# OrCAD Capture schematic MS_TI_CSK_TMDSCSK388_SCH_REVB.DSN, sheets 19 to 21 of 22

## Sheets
19 19.ETHERNET,HDMI & USB: size C; title: ETHERNET,HDMI & USB
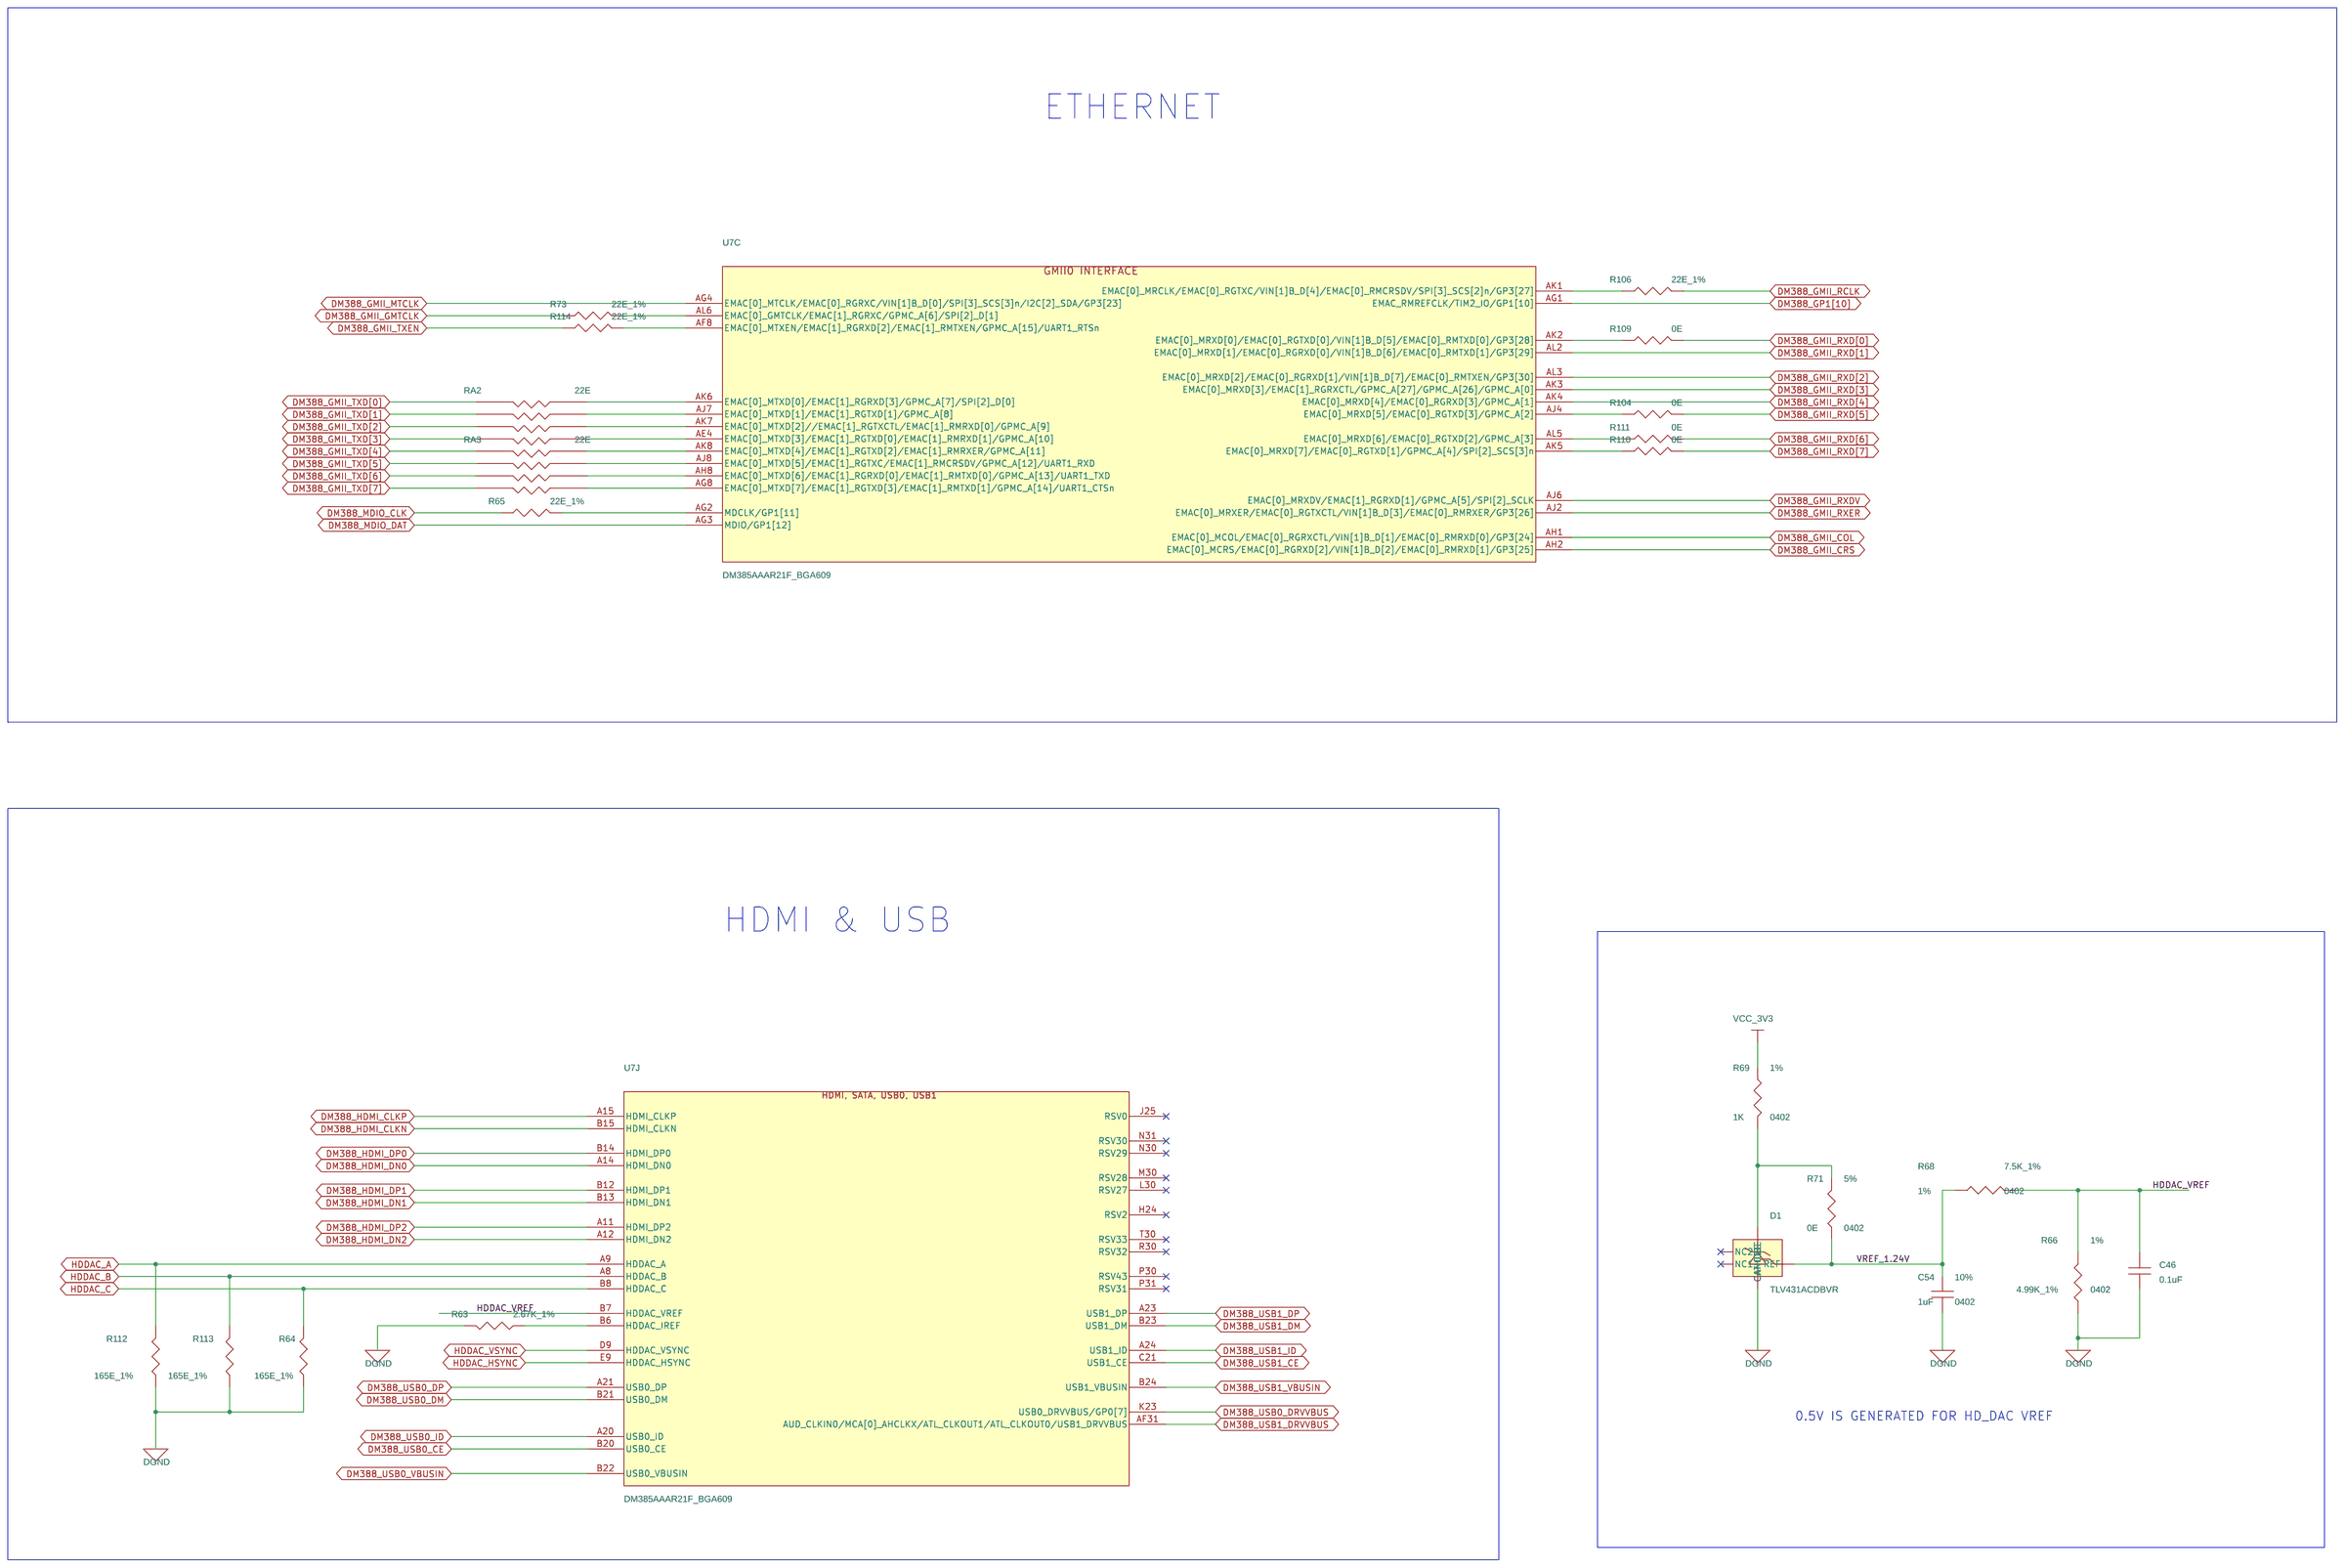
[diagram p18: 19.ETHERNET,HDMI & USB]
20 20.CAMERA,JTAG,CSI: size C; title: CAMERA,JTAG,CSI
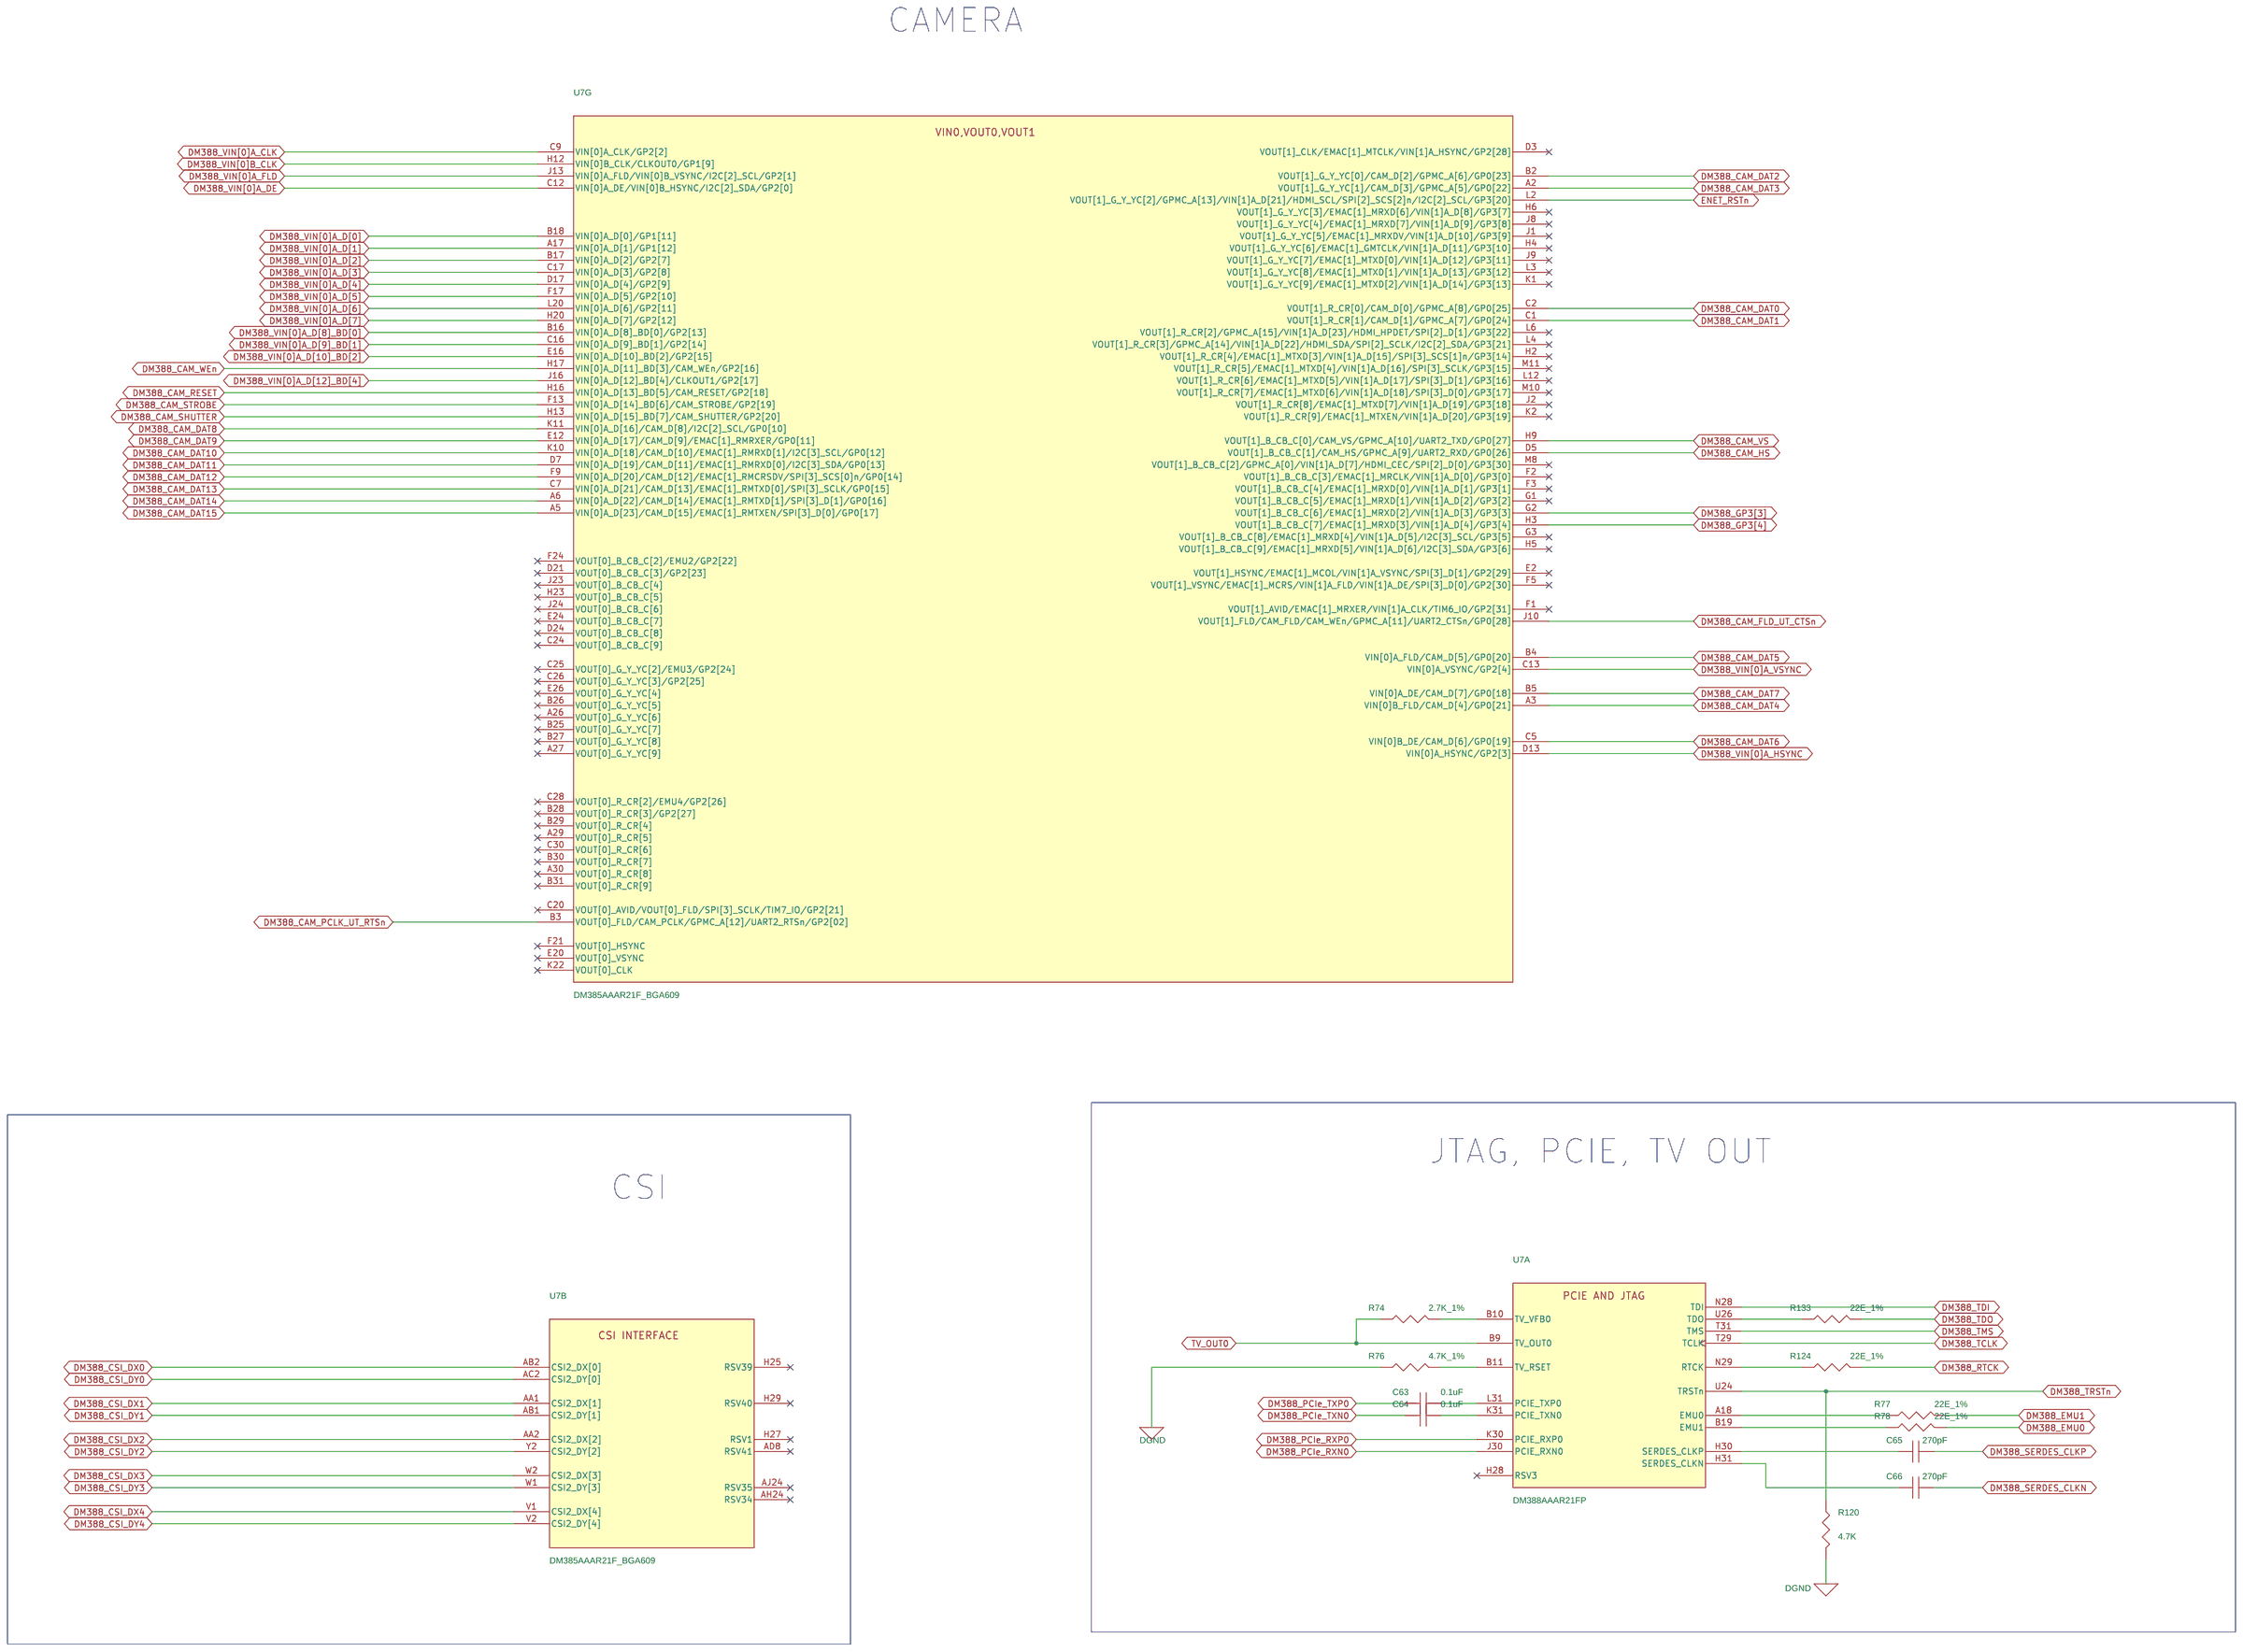
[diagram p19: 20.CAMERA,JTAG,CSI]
21 21.BOARD TO BOARD CONNECTORS: size C; title: BOARD TO BOARD CONNECTORS
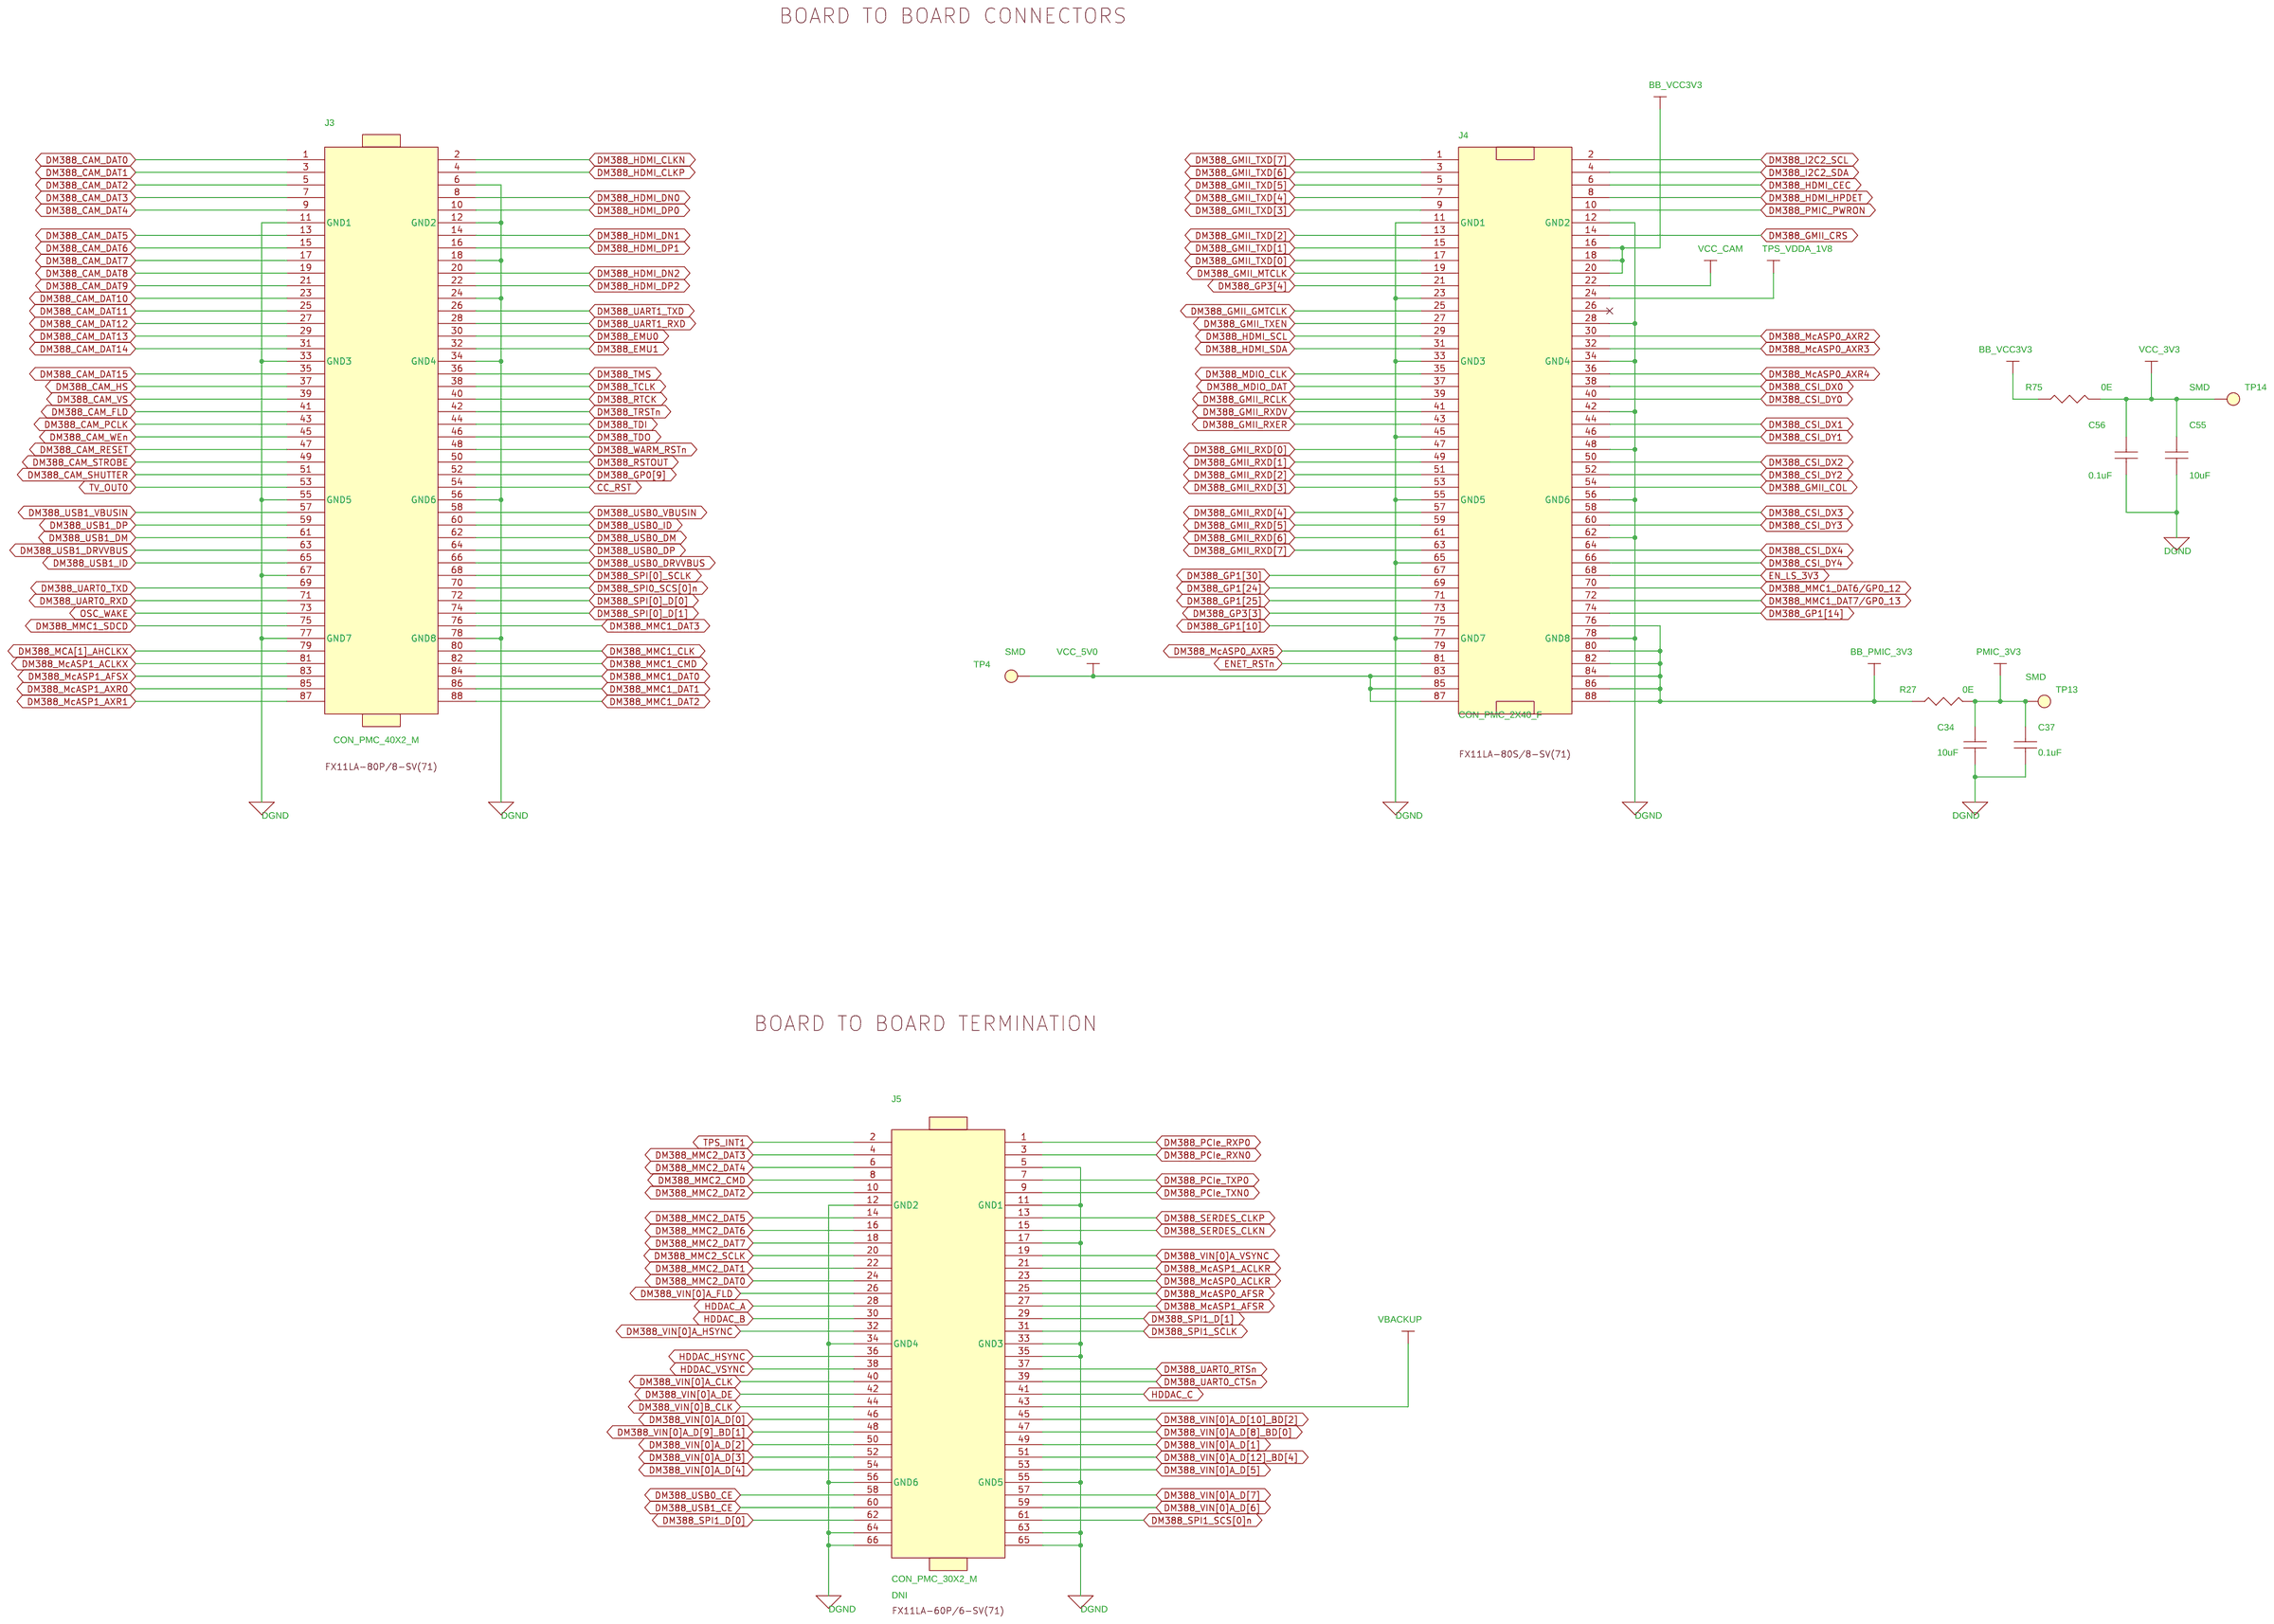
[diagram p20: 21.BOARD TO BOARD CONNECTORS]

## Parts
sheet 19.ETHERNET,HDMI & USB
C46  0.1uF  [CAP0402]
C54  1uF  [CAP0402]
D1  TLV431ACDBVR  [SOT23-5]
R63  2.67K_1%  [RES0402]
R64  165E_1%  [RES0402]
R65  22E_1%  [RES0402]
R66  4.99K_1%  [RES0402]
R68  7.5K_1%  [RES0402]
R69  1K  [RES0402]
R71  0E  [RES0402]
R73  22E_1%  [RES0402]
R104  0E  [RES0402]
R106  22E_1%  [RES0402]
R109  0E  [RES0402]
R110  0E  [RES0402]
R111  0E  [RES0402]
R112  165E_1%  [RES0402]
R113  165E_1%  [RES0402]
R114  22E_1%  [RES0402]
RA2  22E  [RESA_0402-4]
RA3  22E  [RESA_0402-4]
U7  DM388AAAR21FP  [BGA609_19-68_635X635]  (sections A,B,C,D,E,F,G,H,I,J,K,L,M,N)
sheet 20.CAMERA,JTAG,CSI
C63  0.1uF  [CAP0402]
C64  0.1uF  [CAP0402]
C65  270pF  [CAP0402]
C66  270pF  [CAP0402]
R74  2.7K_1%  [RES0402]
R76  4.7K_1%  [RES0402]
R77  22E_1%  [RES0402]
R78  22E_1%  [RES0402]
R120  4.7K  [RES0402]
R124  22E_1%  [RES0402]
R133  22E_1%  [RES0402]
sheet 21.BOARD TO BOARD CONNECTORS
C34  10uF  [CAP0603]
C37  0.1uF  [CAP0201]
C55  10uF  [CAP0603]
C56  0.1uF  [CAP0201]
J3  CON_PMC_40X2_M  [CON_PMC40X2_FX11LA-80P_P_S_S]
J4  CON_PMC_2X40_F  [CON_PMC40X2_FX11LA-80S_S_S_S]
J5  CON_PMC_30X2_M  [CON_PMC30X2_FX11LA-60P_P_S_S]
R27  0E  [RES0402]
R75  0E  [RES0402]
TP4  SMD  [TP40_SMD]
TP13  SMD  [TP40_SMD]
TP14  SMD  [TP40_SMD]

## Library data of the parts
C46 = CAP: CAP CERAMIC 0.1uF 25V -20% TO +80 Y5V 0402; Chkd/date: SHREESHAIL/301105; Crtd /date: MAZHAR/251005; Custom_Duty: 15%; Customs_HS_Code: 85322990; Distributor_name: DIGIKEY; Distributor_part_number: 490-3271-1-ND; Height: 0.55MM; Mfr_name: MURATA; Mfr_part_number: GRM155F51E104ZA01D; Mistral Part No: 120009030085; Package: 0402; Part_type: CAPACITORS\CERAMIC; Project: ADR; Tolerance: -20% TO +80%; Voltage: 25V; Datasheet: Y:\MIS_DATABASE\DATASHEETS\CAPACITORS\GRM188SERIES.PDF
C54 = CAP: CAP CERAMIC 1uF 16V 10% X5R 0402; Chkd/date: RAGESH/050511; Crtd /date: BAVISH/030511; Custom_Duty: 15%; Customs_HS_Code: 85322990; Distributor_name: DIGIKEY; Distributor_part_number: 445-4978-1-ND; Height: 0.55MM; Mfr_name: TDK CORPORATION; Mfr_part_number: C1005X5R1C105K; Mistral Part No: 120011050002-R; Package: 0402; Part_type: CAPACITORS\CERAMIC; Project: TE_MODULE; RoHS: RoHS; Temperature: -55°C+85°C; Tolerance: 10%; Voltage: 16V; Wattage: NA; Weight: NA; Datasheet: Y:\MIS_DATABASE\DATASHEETS\CAPACITORS\TDK_C-SERIES.PDF
D1 = TLV431AQDBVR_SOT23-5: IC LOW VOLTAGE ADJUSTABLE PRECISION SHUNT REGULATORS SOT23-5; Chkd/date: NAVEED/241114; Crtd /date: VASANTHA/281014; Custom_Duty: 15%; Customs_HS_Code: 85423100; Distributor_name: DIGIKEY; Distributor_part_number: 296-1348-1-ND; Height: 1.45MM; Mfr_name: TEXAS INSTRUMENTS; Mistral Part No: 142014100024-R; Part_type: ICS\POWER\VOLTAGE REGULATOR; Project: GALILEO_EVM; RoHS: RoHS; Temperature: -0°C+70°C; Tolerance: NA; Voltage: NA; Wattage: NA; Weight: NA; Datasheet: Y:\MIS_DATABASE\DATASHEETS\MISC\REGULATORS\TLV431.PDF
R63 = RESISTOR: RES 2.67K 1/10W 1% 0402; Chkd/date: USMAN/160112; Crtd /date: CHAITHANYA/160112; Custom_Duty: 15%; Customs_HS_Code: 85332119; Distributor_name: DIGIKEY; Distributor_part_number: P2.67KLCT-ND; Height: 0.40MM; Mfr_name: PANASONIC; Mfr_part_number: ERJ-2RKF2671X; Mistral Part No: 110012010012-R; Package: 0402; Part_type: RESISTORS\FIXED; Project: DM385EVM_BASE-BOARD; RoHS: RoHS; Temperature: -55°C+155°C; Tolerance: 1%; Voltage: NA; Wattage: 1/10W; Weight: 0.8/1000g; Datasheet: Y:\MIS_DATABASE\DATASHEETS\RESISTORS\PAN-ERJSERIES1.PDF
R64 R112 R113 = RESISTOR: RES 165E 1/16W 1% 0402; Chkd/date: SUHAS/200411; Crtd /date: MAZHAR/180411; Custom_Duty: 15%; Customs_HS_Code: 85332119; Distributor_name: DIGIKEY; Distributor_part_number: P165LCT-ND; Height: 0.40MM; Mfr_name: PANASONIC-ECG; Mfr_part_number: ERJ-2RKF1650X; Mistral Part No: 110011040012-R; Package: 0402; Part_type: RESISTORS\FIXED; Project: AM4515_EVM_LCD; RoHS: RoHS; Temperature: -55°C+125°C; Tolerance: 1%; Voltage: NA; Wattage: 1/16W; Weight: 0.8/1000g; Datasheet: Y:\MIS_DATABASE\DATASHEETS\RESISTORS\PAN-ERJSERIES.PDF
R65 R77 R78 R124 R133 = RESISTOR: RES 22E 1/16W 1% 0402; Alternate_mfr_name_A: VISHAY; Alternate_mfr_part_number_A: CRCW040222R0FKED; Chkd/date: SUHAS/290910; Crtd /date: MAZHAR/090909; Cust_part_number: 4700-80047E; Custom_Duty: 15%; Customs_HS_Code: 85332119; Distributor_name: DIGIKEY; Distributor_name_A: DIGIKEY; Distributor_part_number: 311-22.0LRCT-ND; Distributor_part_number_A: 541-22.0LCT-ND; Height: 0.40MM; Mfr_name: YAGEO AMERICA; Mfr_part_number: RC0402FR-0722RL; Mistral Part No: 110009090004-P; Package: 0402; Part_type: RESISTORS\FIXED; Project: VMEFMCD; Remarks: In alternate datasheet it is RoHS COMPLIANT. Y:\MIS_DATABASE\DATASHEETS\RESISTORS\CRCW0402.PDF; RoHS: Pb-Free; Temperature: -55°C+155°C; Tolerance: 1%; Voltage: 50V; Wattage: 1/16W; Weight: 0.8g/1000pcs; Datasheet: Y:\MIS_DATABASE\DATASHEETS\RESISTORS\YAGEO-RC0402.PDF
R66 = RESISTOR: RES 4.99K 1/10W 1% 0402; Alternate_mfr_name_A: YAGEO CORPORATION; Alternate_mfr_part_number_A: RT0402FRE074K99L; Chkd/date: NAVEED/140115; Crtd /date: MAZHAR/150506; Customs_HS_Code: YES; Distributor_name: DIGIKEY; Distributor_name_A: DIGIKEY; Distributor_part_number: P4.99KLCT-ND; Distributor_part_number_A: RT0402FRE074K99L-ND; Height: 0.40MM; Mfr_name: PANASONIC-ECG; Mfr_part_number: ERJ-2RKF4991X; Mistral Part No: 110009030808-R; Package: 0402; Part_type: RESISTORS\FIXED; Project: VOCERA; RoHS: RoHS; Temperature: -55°C+155°C; Tolerance: 1%; Wattage: 1/16W; Datasheet: Y:\MIS_DATABASE\DATASHEETS\RESISTORS\ERJ-2R.PDF
R68 = RESISTOR: RES 7.5K 1/16W 1% 0402; Chkd/date: SHREESHAIL/24050; Crtd /date: MAZHAR/020806; Custom_Duty: 15%; Customs_HS_Code: 85332119; Distributor_name: DIGIKEY; Distributor_part_number: P7.50KLCT-ND; Height: 0.40MM; Mfr_name: PANASONIC-ECG; Mfr_part_number: ERJ-2RKF7501X; Mistral Part No: 110009031094-R; Package: 0402; Part_type: RESISTORS\FIXED; Project: RED EYE; RoHS: RoHS; Tolerance: 1%; Wattage: 1/16W; Datasheet: Y:\MIS_DATABASE\DATASHEETS\RESISTORS\PAN_ERJ.PDF
R69 = RESISTOR: RES 1K 1/16W 1% 0402; Alternate_mfr_name_A: AVX CORPORATION; Alternate_mfr_name_C: YAGEO AMERICA; Alternate_mfr_name_D: VISHAY; Alternate_mfr_part_number_A: CR05-102F-H; Alternate_mfr_part_number_C: RC0402FR-071KL; Alternate_mfr_part_number_D: CRCW04021K00FKED; Chkd/date: SHREESHAIL/210506; Crtd /date: MAZHAR/150506; Cust_part_number: 4700-80039E; Custom_Duty: 15%; Customs_HS_Code: 85332119; Distributor_name: DIGIKEY; Distributor_name_A: NA; Distributor_name_C: DIGIKEY; Distributor_name_D: DIGIKEY; Distributor_part_number: P1.00KLCT-ND; Distributor_part_number_A: NA; Distributor_part_number_C: 311-1.00KLRCT-ND; Distributor_part_number_D: 541-1.00KLCT-ND; Height: 0.40MM; Mfr_name: PANASONIC-ECG; Mfr_part_number: ERJ-2RKF1001X; Mistral Part No: 110009030411-R; Package: 0402; Part_type: RESISTORS\FIXED; Project: VOCERA; RoHS: RoHS; Tolerance: 1%; Wattage: 1/16W; Datasheet: Y:\MIS_DATABASE\DATASHEETS\RESISTORS\PAN_ERJ.PDF
R27 R71 R75 = RESISTOR: RES 0E 1/10W 5% 0402; Chkd/date: NAVEED/241114; Crtd /date: NAVEED/201014; Custom_Duty: 15%; Customs_HS_Code: 85332119; Distributor_name: DIGIKEY; Distributor_part_number: P0.0JCT-ND; Height: 0.40MM; Mfr_name: PANASONIC-ECG; Mfr_part_number: ERJ-2GE0R00X; Mistral Part No: 110014100008-R; Package: 0402; Part_type: RESISTORS\FIXED; Project: AEGIS POM; RoHS: RoHS; SIGNAL_MODEL: RESISTOR_RES0402_0E_0E; Tolerance: 5%; Wattage: 1/10W; Datasheet: Y:\MIS_DATABASE\DATASHEETS\RESISTORS\ERJ12.PDF
R73 R106 R114 = RESISTOR: RES 22E 1/16W 1% 0402; Alternate_mfr_name_A: VISHAY; Alternate_mfr_part_number_A: CRCW040222R0FKED; Chkd/date: SUHAS/290910; Crtd /date: MAZHAR/090909; Cust_part_number: 4700-80047E; Custom_Duty: 15%; Customs_HS_Code: 85332119; Distributor_name: DIGIKEY; Distributor_name_A: DIGIKEY; Distributor_part_number: 311-22.0LRCT-ND; Distributor_part_number_A: 541-22.0LCT-ND; Height: 0.40MM; Mfr_name: YAGEO AMERICA; Mfr_part_number: RC0402FR-0722RL; Mistral Part No: 110009090004-P; Package: 0402; Part_type: RESISTORS\FIXED; Project: VMEFMCD; Remarks: In alternate datasheet it is RoHS COMPLIANT. Y:\MIS_DATABASE\DATASHEETS\RESISTORS\CRCW0402.PDF; RoHS: Pb-Free; SIGNAL_MODEL: RESISTOR_RES0402_22E_1%_22E_1%; Temperature: -55°C+155°C; Tolerance: 1%; Voltage: 50V; Wattage: 1/16W; Weight: 0.8g/1000pcs; Datasheet: Y:\MIS_DATABASE\DATASHEETS\RESISTORS\YAGEO-RC0402.PDF
R104 R109-R111 = RESISTOR: RES 0E 1/16W 5% 0402; Chkd/date: USMAN240712; Crtd /date: CHAITHANYA/300911; Custom_Duty: 15%; Customs_HS_Code: 85332119; Distributor_name: DIGIKEY; Distributor_part_number: 311-0.0JRCT-ND; Height: 0.40MM; Mfr_name: YAGEO; Mfr_part_number: RC0402JR-070RL; Mistral Part No: 110011090036-R; Package: 0402; Part_type: RESISTORS\FIXED; Project: VP-4000-PROCESSOR; RoHS: RoHS; SIGNAL_MODEL: RESISTOR_RES0402_0E_0E; Temperature: -55°C+155°C; Tolerance: 5%; Voltage: NA; Wattage: 1/16W; Weight: NA; Datasheet: Y:\MIS_DATABASE\DATASHEETS\RESISTORS\YAGEO_RC0402JR.PDF
RA2 RA3 = RESARR_ISO4: RES ARRAY 22E 31mW 5% 0402; Chkd/date: MAZHAR/291208; Crtd /date: USMAN/261108; Distributor_name: DIGIKEY; Distributor_part_number: Y7220CT-ND; Height: 0.45MM; Mfr_name: PANASONIC-ECG; Mfr_part_number: EXB-28V220JX; Mistral Part No: 110009030021-R; Package: 0402; Part_type: RESISTORS\ARRAY; Project: KHAN_MAIN; RoHS: RoHS; SIGNAL_MODEL: RESARR_ISO4_RESA_0402-4_22E_22E; Tolerance: 5%; Wattage: 31mW; Datasheet: Y:\MIS_DATABASE\DATASHEETS\RESISTORS\EXB-2HV.PDF
U7 = DM385AAAR21F_BGA609: IC PROCESSOR DIGITAL MEDIA FCBGA609; Chkd/date: VASANTHA/170516; Color: Default; Crtd /date: VASANTHA/170516; Custom_Duty: 15%; Customs_HS_Code: 85423100; Distributor_name: NA; Distributor_part_number: NA; Height: 1.32MM; Location X-Coordinate: 0; Location Y-Coordinate: 0; Mfr_name: TEXAS INSTRUMENTS; Mistral Part No: 141216050002-R; Package: FCBGA609; Part_type: ICS\DIGITAL\MICROPROCESSOR; Power Pins Visible: False; Primitive: DEFAULT; Project: TMDXCSK388; RoHS: RoHS; Temperature: 0°C+95°C; Tolerance: NA; Voltage: NA; Wattage: NA; Weight: NA; Datasheet: Y:\MIS_DATABASE\DATASHEETS\ICS\DIGITAL\MICROCONTROLLER\DM385-88.PDF
C63 C64 = CAP: CAP CERAMIC 0.1uF 16V 10% X7R 0402; Alternate_mfr_name_A: KEMET; Alternate_mfr_part_number_A: C0402C104K4RACT; Chkd/date: MAZHAR/281108; Crtd /date: MAZHAR/030907; Cust_part_number: 1500-80042E; Custom_Duty: 15%; Customs_HS_Code: 85322990; Distributor_name: DIGIKEY; Distributor_name_A: DIGIKEY; Distributor_part_number: 490-3261-1-ND; Distributor_part_number_A: 399-3521-1-ND; Height: 0.55MM; Mfr_name: MURATA; Mfr_part_number: GRM155R71C104KA88D; Mistral Part No: 120009030060-R; Package: 0402; Part_type: CAPACITORS\CERAMIC; Project: SMART VIEW_IP CAMERA; Tolerance: 10%; Voltage: 16V; Wattage: NA; Weight: NA; Datasheet: Y:\MIS_DATABASE\DATASHEETS\CAPACITORS\GRM188SERIES.PDF
C65 C66 = CAP: CAP CERAMIC 270pF 50V 10% X7R 0402; Chkd/date: VASANTHA/120516; Crtd /date: VASANTHA/120516; Custom_Duty: 15%; Customs_HS_Code: 85322990; Distributor_name: DIGIKEY; Distributor_part_number: 490-1299-1-ND; Height: 0.55MM; Mfr_name: MURATA; Mfr_part_number: GRM155R71H271KA01D; Mistral Part No: 120009030344-R; Package: 0402; Part_type: CAPACITORS\CERAMIC; Project: TMDXCSK368; RoHS: RoHS; Temperature: -55°C+125°C; Tolerance: 10%; Voltage: 50V; Wattage: NA; Weight: NA; Datasheet: Y:\MIS_DATABASE\DATASHEETS\CAPACITORS\GRM188SERIES.PDF
R74 = RESISTOR: RES 2.7K 1/16W 1% 0402; Alternate_mfr_name_A: VISHAY; Alternate_mfr_name_B: PANASONIC-ECG; Alternate_mfr_part_number_A: CRCW04022K70FKED; Alternate_mfr_part_number_B: ERA-2AED272X; Chkd/date: SUHAS/290910; Crtd /date: MAZHAR/280809; Custom_Duty: 15%; Customs_HS_Code: 85332119; Distributor_name: DIGIKEY; Distributor_part_number: 311-2.70KLRCT-ND; Height: 0.40MM; Mfr_name: YAGEO AMERICA; Mfr_part_number: RC0402FR-072K7L; Mistral Part No: 110009080028-P; Package: 0402; Part_type: RESISTORS\FIXED; Project: STORM2; RoHS: Pb-Free; Temperature: -55°C+155°C; Tolerance: 1%; Voltage: 50V; Wattage: 1/16W; Weight: 0.8g/1000pcs; Datasheet: Y:\MIS_DATABASE\DATASHEETS\RESISTORS\YAGEO-RC0402.PDF
R76 = RESISTOR: RES 4.7K 1/16W 1% 0402; Alternate_mfr_name_B: PANASONIC-ECG-ECG; Alternate_mfr_name_C: YAGEO AMERICA; Alternate_mfr_part_number_B: ERJ-S02F4701V; Alternate_mfr_part_number_C: RC0402FR-074K7L; Chkd/date: MAZHAR/130709; Crtd /date: USMAN/070109; Custom_Duty: 15%; Customs_HS_Code: 85332119; Distributor_name: DIGIKEY; Distributor_name_B: NA; Distributor_name_C: NA; Distributor_part_number: 541-4.70KLCT-ND; Distributor_part_number_B: NA; Distributor_part_number_C: NA; Height: 0.40MM; Mfr_name: VISHAY; Mfr_part_number: CRCW04024K70FKED; Mistral Part No: 110009030797-P; Package: 0402; Part_type: RESISTORS\FIXED; Project: OMAP_EVM; RoHS: Pb-Free; Tolerance: 1%; Wattage: 1/16W; Datasheet: Y:\MIS_DATABASE\DATASHEETS\RESISTORS\CRCW0603.PDF
R120 = RESISTOR: RES 4.7K 1/16W 5% 0402; Chkd/date: VASANTHA/130516; Crtd /date: VASANTHA/130516; Custom_Duty: 15%; Customs_HS_Code: 85332119; Distributor_name: DIGIKEY; Distributor_part_number: 311-4.7KJRCT-ND; Height: 0.55MM; Mfr_name: YAGEO AMERICA; Mfr_part_number: RC0402JR-074K7L; Mistral Part No: 110009030792-R; Package: 0402; Part_type: RESISTORS\FIXED; Project: TMDXCSK368; RoHS: RoHS; Temperature: -55°C+155°C; Tolerance: 5%; Voltage: NA; Wattage: 1/16W; Weight: NA; Datasheet: Y:\MIS_DATABASE\DATASHEETS\RESISTORS\YAGEO-RC0402.PDF
C34 C55 = CAP: CAP CERAMIC 10uF 10V 20% X5R 0603; Chkd/date: VASANTHA/120516; Crtd /date: VASANTHA/120516; Custom_Duty: 15%; Customs_HS_Code: 85322990; Distributor_name: DIGIKEY; Distributor_part_number: 490-10475-1-ND; Height: 0.90MM; Mfr_name: MURATA; Mfr_part_number: GRM188R61A106ME69D; Mistral Part No: 120009050022-R; Package: 0603; Part_type: CAPACITORS\CERAMIC; Project: TMDXCSK368; RoHS: RoHS; Temperature: -55°C+85°C; Tolerance: 20%; Voltage: 10V; Wattage: NA; Weight: NA; Datasheet: Y:\MIS_DATABASE\DATASHEETS\CAPACITORS\GRM188SERIES.PDF
C37 C56 = CAP: CAP CERAMIC 0.1uF 10V 20% X5R 0201; Chkd/date: RAGESH/290910; Crtd /date: MUDDU/290410; Custom_Duty: 15%; Customs_HS_Code: 85322990; Distributor_name: DIGIKEY; Distributor_part_number: 490-5405-1-ND; Height: 0.33MM; Mfr_name: MURATA; Mfr_part_number: GRM033R61A104ME15D; Mistral Part No: 120010040004-R; Package: 0201; Part_type: CAPACITORS\CERAMIC; Project: BUG_BASE-II; RoHS: RoHS; Temperature: -55°C+85°C; Tolerance: 20%; Voltage: 10V; Weight: NA; Datasheet: Y:\MIS_DATABASE\DATASHEETS\CAPACITORS\MURATA_CMCC.PDF
J3 = CON_PMC40X2_FX11LA_M: CON PMC 40X2 0.5MM  PITCH MALE ST SMD; Chkd/date: MAZHAR/050308; Crtd /date: USMAN/040308; Custom_Duty: 24%; Customs_HS_Code: 85369090; Distributor_name: DIGIKEY; Distributor_part_number: H10769-ND; Height: 2.20MM; Mfr_name: HIROSE ELECTRIC EUROPE; Mfr_part_number: FX11LA-80P/8-SV(71); Mistral Part No: 150009030615; Package: SMD; Part_type: CONNECTOR\PMC; Project: 3430_0-65MM; Datasheet: Y:\MIS_DATABASE\DATASHEETS\CONNECTORS\0.5FX11LA.PDF
J4 = CON_PMC_FX11LA-80S: CON PMC 2X40 0.5MM  PITCH FEMALE ST SMD; Chkd/date: VASANTHA/040616; Crtd /date: VASANTHA/040616; Custom_Duty: 24%; Customs_HS_Code: 85369090; Distributor_name: DIGIKEY; Distributor_part_number: H10777-ND; Height: 1.95MM; Mfr_name: HIROSE ELECTRIC EUROPE; Mfr_part_number: FX11LA-80S/8-SV(71); Mistral Part No: 150016070001-R; Package: SMD; Part_type: CONNECTOR\PMC; Project: TMDXCSKCC; RoHS: RoHS; Temperature: -55°C+85°C; Tolerance: NA; Voltage: NA; Wattage: NA; Weight: NA; Datasheet: Y:\MIS_DATABASE\DATASHEETS\CONNECTORS\0.5FX11LA.PDF
J5 = CON_PMC30X2_FX11LA_M: CON PMC 30X2 0.5MM  PITCH MALE ST SMD; Chkd/date: MAZHAR/050308; Crtd /date: USMAN/040308; Custom_Duty: 24%; Customs_HS_Code: 85369090; Distributor_name: DIGIKEY; Distributor_part_number: H10768-ND; Height: 2.20MM; Loading: DNI; Mfr_name: HIROSE ELECTRIC EUROPE; Mfr_part_number: FX11LA-60P/6-SV(71); Mistral Part No: 150009030608; Package: SMD; Part_type: CONNECTOR\PMC; Project: 3430_0-65MM; Datasheet: Y:\MIS_DATABASE\DATASHEETS\CONNECTORS\0.5FX11LA.PDF
TP4 TP13 TP14 = TESTPOINT: TESTPOINT 40 SMD; Chkd/date: MAZHAR/190505; Crtd /date: MAZHAR/190505; Distributor_name: NA; Distributor_part_number: NA; Height: NA; Mfr_name: LOCAL; Mistral Part No: 130009030933; Part_type: MISC\TESTPOINT; Project: RAINIER-3

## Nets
DGND: C34.2 C37.2 C46.1 C54.2 C55.2 C56.2 D1.5(ANODE) J3.6 J3.11(GND1) J3.12(GND2) J3.18 J3.24 J3.33(GND3) J3.34(GND4) J3.55(GND5) J3.56(GND6) J3.67 J3.77(GND7) J3.78(GND8) J4.11(GND1) J4.12(GND2) J4.23 J4.28 J4.33(GND3) J4.34(GND4) J4.42 J4.45 J4.48 J4.55(GND5) J4.56(GND6) J4.62 J4.65 J4.77(GND7) J4.78(GND8) J5.5 J5.11(GND1) J5.12(GND2) J5.17 J5.33(GND3) J5.34(GND4) J5.35 J5.55(GND5) J5.56(GND6) J5.63 J5.64 J5.65 J5.66 R63.2 R64.1 R66.1 R76.1 R112.1 R113.1 R120.2 ; also on sheet 9 10 11 12 13 14 15 16 17 18
VCC_3V3: C55.1 C56.1 R69.1 R75.1 TP14.1(TP) ; also on sheet 9 10 12 13 14 16 17 18 22
VCC_5V0: J4.83 J4.85 J4.87 TP4.1(TP) ; also on sheet 16 17 18
VCC_CAM: J4.22 ; also on sheet 14
BB_PMIC_3V3: J4.76 J4.80 J4.82 J4.84 J4.86 J4.88 R27.2
BB_VCC3V3: J4.16 J4.18 J4.20 R75.2
CC_RST: J3.54 ; also on sheet 9
DM388_CAM_DAT0: J3.1 U7.C2(VOUT[1]_R_CR[0]/CAM_D[0]/GPMC_A[8]/GP0[25])
DM388_CAM_DAT1: J3.3 U7.C1(VOUT[1]_R_CR[1]/CAM_D[1]/GPMC_A[7]/GP0[24])
DM388_CAM_DAT2: J3.5 U7.B2(VOUT[1]_G_Y_YC[0]/CAM_D[2]/GPMC_A[6]/GP0[23])
DM388_CAM_DAT3: J3.7 U7.A2(VOUT[1]_G_Y_YC[1]/CAM_D[3]/GPMC_A[5]/GP0[22])
DM388_CAM_DAT4: J3.9 U7.A3(VIN[0]B_FLD/CAM_D[4]/GP0[21])
DM388_CAM_DAT5: J3.13 U7.B4(VIN[0]A_FLD/CAM_D[5]/GP0[20])
DM388_CAM_DAT6: J3.15 U7.C5(VIN[0]B_DE/CAM_D[6]/GP0[19])
DM388_CAM_DAT7: J3.17 U7.B5(VIN[0]A_DE/CAM_D[7]/GP0[18])
DM388_CAM_DAT8: J3.19 U7.K11(VIN[0]A_D[16]/CAM_D[8]/I2C[2]_SCL/GP0[10])
DM388_CAM_DAT9: J3.21 U7.E12(VIN[0]A_D[17]/CAM_D[9]/EMAC[1]_RMRXER/GP0[11])
DM388_CAM_DAT10: J3.23 U7.K10(VIN[0]A_D[18]/CAM_D[10]/EMAC[1]_RMRXD[1]/I2C[3]_SCL/GP0[12])
DM388_CAM_DAT11: J3.25 U7.D7(VIN[0]A_D[19]/CAM_D[11]/EMAC[1]_RMRXD[0]/I2C[3]_SDA/GP0[13])
DM388_CAM_DAT12: J3.27 U7.F9(VIN[0]A_D[20]/CAM_D[12]/EMAC[1]_RMCRSDV/SPI[3]_SCS[0]n/GP0[14])
DM388_CAM_DAT13: J3.29 U7.C7(VIN[0]A_D[21]/CAM_D[13]/EMAC[1]_RMTXD[0]/SPI[3]_SCLK/GP0[15])
DM388_CAM_DAT14: J3.31 U7.A6(VIN[0]A_D[22]/CAM_D[14]/EMAC[1]_RMTXD[1]/SPI[3]_D[1]/GP0[16])
DM388_CAM_DAT15: J3.35 U7.A5(VIN[0]A_D[23]/CAM_D[15]/EMAC[1]_RMTXEN/SPI[3]_D[0]/GP0[17])
DM388_CAM_FLD: J3.41 ; also on sheet 12
DM388_CAM_FLD_UT_CTSn: U7.J10(VOUT[1]_FLD/CAM_FLD/CAM_WEn/GPMC_A[11]/UART2_CTSn/GP0[28]) ; also on sheet 12
DM388_CAM_HS: J3.37 U7.D5(VOUT[1]_B_CB_C[1]/CAM_HS/GPMC_A[9]/UART2_RXD/GP0[26])
DM388_CAM_PCLK: J3.43 ; also on sheet 12
DM388_CAM_PCLK_UT_RTSn: U7.B3(VOUT[0]_FLD/CAM_PCLK/GPMC_A[12]/UART2_RTSn/GP2[02]) ; also on sheet 12
DM388_CAM_RESET: J3.47 U7.H16(VIN[0]A_D[13]_BD[5]/CAM_RESET/GP2[18])
DM388_CAM_SHUTTER: J3.51 U7.H13(VIN[0]A_D[15]_BD[7]/CAM_SHUTTER/GP2[20])
DM388_CAM_STROBE: J3.49 U7.F13(VIN[0]A_D[14]_BD[6]/CAM_STROBE/GP2[19])
DM388_CAM_VS: J3.39 U7.H9(VOUT[1]_B_CB_C[0]/CAM_VS/GPMC_A[10]/UART2_TXD/GP0[27])
DM388_CAM_WEn: J3.45 U7.H17(VIN[0]A_D[11]_BD[3]/CAM_WEn/GP2[16])
DM388_CSI_DX0: J4.38 U7.AB2(CSI2_DX[0])
DM388_CSI_DX1: J4.44 U7.AA1(CSI2_DX[1])
DM388_CSI_DX2: J4.50 U7.AA2(CSI2_DX[2])
DM388_CSI_DX3: J4.58 U7.W2(CSI2_DX[3])
DM388_CSI_DX4: J4.64 U7.V1(CSI2_DX[4])
DM388_CSI_DY0: J4.40 U7.AC2(CSI2_DY[0])
DM388_CSI_DY1: J4.46 U7.AB1(CSI2_DY[1])
DM388_CSI_DY2: J4.52 U7.Y2(CSI2_DY[2])
DM388_CSI_DY3: J4.60 U7.W1(CSI2_DY[3])
DM388_CSI_DY4: J4.66 U7.V2(CSI2_DY[4])
DM388_EMU0: J3.30 R78.2
DM388_EMU1: J3.32 R77.2
DM388_GMII_COL: J4.54 U7.AH1(EMAC[0]_MCOL/EMAC[0]_RGRXCTL/VIN[1]B_D[1]/EMAC[0]_RMRXD[0]/GP3[24])
DM388_GMII_CRS: J4.14 U7.AH2(EMAC[0]_MCRS/EMAC[0]_RGRXD[2]/VIN[1]B_D[2]/EMAC[0]_RMRXD[1]/GP3[25])
DM388_GMII_GMTCLK: J4.25 R73.1
DM388_GMII_MTCLK: J4.19 U7.AG4(EMAC[0]_MTCLK/EMAC[0]_RGRXC/VIN[1]B_D[0]/SPI[3]_SCS[3]n/I2C[2]_SDA/GP3[23])
DM388_GMII_RCLK: J4.39 R106.2
DM388_GMII_RXD[0]: J4.47 R109.2
DM388_GMII_RXD[1]: J4.49 U7.AL2(EMAC[0]_MRXD[1]/EMAC[0]_RGRXD[0]/VIN[1]B_D[6]/EMAC[0]_RMTXD[1]/GP3[29])
DM388_GMII_RXD[2]: J4.51 U7.AL3(EMAC[0]_MRXD[2]/EMAC[0]_RGRXD[1]/VIN[1]B_D[7]/EMAC[0]_RMTXEN/GP3[30])
DM388_GMII_RXD[3]: J4.53 U7.AK3(EMAC[0]_MRXD[3]/EMAC[1]_RGRXCTL/GPMC_A[27]/GPMC_A[26]/GPMC_A[0])
DM388_GMII_RXD[4]: J4.57 U7.AK4(EMAC[0]_MRXD[4]/EMAC[0]_RGRXD[3]/GPMC_A[1])
DM388_GMII_RXD[5]: J4.59 R104.2
DM388_GMII_RXD[6]: J4.61 R111.2
DM388_GMII_RXD[7]: J4.63 R110.2
DM388_GMII_RXDV: J4.41 U7.AJ6(EMAC[0]_MRXDV/EMAC[1]_RGRXD[1]/GPMC_A[5]/SPI[2]_SCLK)
DM388_GMII_RXER: J4.43 U7.AJ2(EMAC[0]_MRXER/EMAC[0]_RGTXCTL/VIN[1]B_D[3]/EMAC[0]_RMRXER/GP3[26])
DM388_GMII_TXD[0]: J4.17 RA2.5
DM388_GMII_TXD[1]: J4.15 RA2.6
DM388_GMII_TXD[2]: J4.13 RA2.7
DM388_GMII_TXD[3]: J4.9 RA2.8
DM388_GMII_TXD[4]: J4.7 RA3.5
DM388_GMII_TXD[5]: J4.5 RA3.6
DM388_GMII_TXD[6]: J4.3 RA3.7
DM388_GMII_TXD[7]: J4.1 RA3.8
DM388_GMII_TXEN: J4.27 R114.1
DM388_GP0[9]: J3.52 ; also on sheet 22
DM388_GP1[10]: J4.75 U7.AG1(EMAC_RMREFCLK/TIM2_IO/GP1[10])
DM388_GP1[14]: J4.74 ; also on sheet 10
DM388_GP1[24]: J4.69 ; also on sheet 10
DM388_GP1[25]: J4.71 ; also on sheet 10
DM388_GP1[30]: J4.67 ; also on sheet 10
DM388_GP3[3]: J4.73 U7.G2(VOUT[1]_B_CB_C[6]/EMAC[1]_MRXD[2]/VIN[1]A_D[3]/GP3[3])
DM388_GP3[4]: J4.21 U7.H3(VOUT[1]_B_CB_C[7]/EMAC[1]_MRXD[3]/VIN[1]A_D[4]/GP3[4])
DM388_HDMI_CEC: J4.6 ; also on sheet 10
DM388_HDMI_CLKN: J3.2 U7.B15(HDMI_CLKN)
DM388_HDMI_CLKP: J3.4 U7.A15(HDMI_CLKP)
DM388_HDMI_DN0: J3.8 U7.A14(HDMI_DN0)
DM388_HDMI_DN1: J3.14 U7.B13(HDMI_DN1)
DM388_HDMI_DN2: J3.20 U7.A12(HDMI_DN2)
DM388_HDMI_DP0: J3.10 U7.B14(HDMI_DP0)
DM388_HDMI_DP1: J3.16 U7.B12(HDMI_DP1)
DM388_HDMI_DP2: J3.22 U7.A11(HDMI_DP2)
DM388_HDMI_HPDET: J4.8 ; also on sheet 10
DM388_HDMI_SCL: J4.29 ; also on sheet 22
DM388_HDMI_SDA: J4.31 ; also on sheet 22
DM388_I2C2_SCL: J4.2 ; also on sheet 22
DM388_I2C2_SDA: J4.4 ; also on sheet 22
DM388_MCA[1]_AHCLKX: J3.79 ; also on sheet 22
DM388_McASP0_ACLKR: J5.23 ; also on sheet 22
DM388_McASP0_AFSR: J5.25 ; also on sheet 22
DM388_McASP0_AXR2: J4.30 ; also on sheet 22
DM388_McASP0_AXR3: J4.32 ; also on sheet 22
DM388_McASP0_AXR4: J4.36 ; also on sheet 22
DM388_McASP0_AXR5: J4.79 ; also on sheet 22
DM388_McASP1_ACLKR: J5.21 ; also on sheet 22
DM388_McASP1_ACLKX: J3.81 ; also on sheet 22
DM388_McASP1_AFSR: J5.27 ; also on sheet 22
DM388_McASP1_AFSX: J3.83 ; also on sheet 22
DM388_McASP1_AXR0: J3.85 ; also on sheet 22
DM388_McASP1_AXR1: J3.87 ; also on sheet 22
DM388_MDIO_CLK: J4.35 R65.1
DM388_MDIO_DAT: J4.37 U7.AG3(MDIO/GP1[12])
DM388_MMC1_CLK: J3.80 ; also on sheet 22
DM388_MMC1_CMD: J3.82 ; also on sheet 22
DM388_MMC1_DAT0: J3.84 ; also on sheet 22
DM388_MMC1_DAT1: J3.86 ; also on sheet 22
DM388_MMC1_DAT2: J3.88 ; also on sheet 22
DM388_MMC1_DAT3: J3.76 ; also on sheet 22
DM388_MMC1_DAT6/GP0_12: J4.70 ; also on sheet 22
DM388_MMC1_DAT7/GP0_13: J4.72 ; also on sheet 22
DM388_MMC1_SDCD: J3.75 ; also on sheet 22
DM388_MMC2_CMD: J5.8 ; also on sheet 22
DM388_MMC2_DAT0: J5.24 ; also on sheet 22
DM388_MMC2_DAT1: J5.22 ; also on sheet 22
DM388_MMC2_DAT2: J5.10 ; also on sheet 22
DM388_MMC2_DAT3: J5.4 ; also on sheet 22
DM388_MMC2_DAT4: J5.6 ; also on sheet 22
DM388_MMC2_DAT5: J5.14 ; also on sheet 22
DM388_MMC2_DAT6: J5.16 ; also on sheet 22
DM388_MMC2_DAT7: J5.18 ; also on sheet 22
DM388_MMC2_SCLK: J5.20 ; also on sheet 22
DM388_PCIe_RXN0: J5.3 U7.J30(PCIE_RXN0)
DM388_PCIe_RXP0: J5.1 U7.K30(PCIE_RXP0)
DM388_PCIe_TXN0: C64.2 J5.9
DM388_PCIe_TXP0: C63.2 J5.7
DM388_PMIC_PWRON: J4.10 ; also on sheet 17
DM388_RSTOUT: J3.50 ; also on sheet 9
DM388_RTCK: J3.40 R124.2
DM388_SERDES_CLKN: C66.2 J5.15
DM388_SERDES_CLKP: C65.2 J5.13
DM388_SPI0_SCS[0]n: J3.70 ; also on sheet 22
DM388_SPI1_D[0]: J5.62 ; also on sheet 22
DM388_SPI1_D[1]: J5.29 ; also on sheet 22
DM388_SPI1_SCLK: J5.31 ; also on sheet 22
DM388_SPI1_SCS[0]n: J5.61 ; also on sheet 22
DM388_SPI[0]_D[0]: J3.72 ; also on sheet 22
DM388_SPI[0]_D[1]: J3.74 ; also on sheet 22
DM388_SPI[0]_SCLK: J3.68 ; also on sheet 22
DM388_TCLK: J3.38 U7.T29(TCLK)
DM388_TDI: J3.44 U7.N28(TDI)
DM388_TDO: J3.46 R133.2
DM388_TMS: J3.36 U7.T31(TMS)
DM388_TRSTn: J3.42 R120.1 U7.U24(TRSTn)
DM388_UART0_CTSn: J5.39 ; also on sheet 22
DM388_UART0_RTSn: J5.37 ; also on sheet 22
DM388_UART0_RXD: J3.71 ; also on sheet 22
DM388_UART0_TXD: J3.69 ; also on sheet 22
DM388_UART1_RXD: J3.28 ; also on sheet 22
DM388_UART1_TXD: J3.26 ; also on sheet 22
DM388_USB0_CE: J5.58 U7.B20(USB0_CE)
DM388_USB0_DM: J3.62 U7.B21(USB0_DM)
DM388_USB0_DP: J3.64 U7.A21(USB0_DP)
DM388_USB0_DRVVBUS: J3.66 U7.K23(USB0_DRVVBUS/GP0[7])
DM388_USB0_ID: J3.60 U7.A20(USB0_ID)
DM388_USB0_VBUSIN: J3.58 U7.B22(USB0_VBUSIN)
DM388_USB1_CE: J5.60 U7.C21(USB1_CE)
DM388_USB1_DM: J3.61 U7.B23(USB1_DM)
DM388_USB1_DP: J3.59 U7.A23(USB1_DP)
DM388_USB1_DRVVBUS: J3.63 U7.AF31(AUD_CLKIN0/MCA[0]_AHCLKX/ATL_CLKOUT1/ATL_CLKOUT0/USB1_DRVVBUS)
DM388_USB1_ID: J3.65 U7.A24(USB1_ID)
DM388_USB1_VBUSIN: J3.57 U7.B24(USB1_VBUSIN)
DM388_VIN[0]A_CLK: J5.40 U7.C9(VIN[0]A_CLK/GP2[2])
DM388_VIN[0]A_D[0]: J5.46 U7.B18(VIN[0]A_D[0]/GP1[11])
DM388_VIN[0]A_D[1]: J5.49 U7.A17(VIN[0]A_D[1]/GP1[12])
DM388_VIN[0]A_D[2]: J5.50 U7.B17(VIN[0]A_D[2]/GP2[7])
DM388_VIN[0]A_D[3]: J5.52 U7.C17(VIN[0]A_D[3]/GP2[8])
DM388_VIN[0]A_D[4]: J5.54 U7.D17(VIN[0]A_D[4]/GP2[9])
DM388_VIN[0]A_D[5]: J5.53 U7.F17(VIN[0]A_D[5]/GP2[10])
DM388_VIN[0]A_D[6]: J5.59 U7.L20(VIN[0]A_D[6]/GP2[11])
DM388_VIN[0]A_D[7]: J5.57 U7.H20(VIN[0]A_D[7]/GP2[12])
DM388_VIN[0]A_D[8]_BD[0]: J5.47 U7.B16(VIN[0]A_D[8]_BD[0]/GP2[13])
DM388_VIN[0]A_D[9]_BD[1]: J5.48 U7.C16(VIN[0]A_D[9]_BD[1]/GP2[14])
DM388_VIN[0]A_D[10]_BD[2]: J5.45 U7.E16(VIN[0]A_D[10]_BD[2]/GP2[15])
DM388_VIN[0]A_D[12]_BD[4]: J5.51 U7.J16(VIN[0]A_D[12]_BD[4]/CLKOUT1/GP2[17])
DM388_VIN[0]A_DE: J5.42 U7.C12(VIN[0]A_DE/VIN[0]B_HSYNC/I2C[2]_SDA/GP2[0])
DM388_VIN[0]A_FLD: J5.26 U7.J13(VIN[0]A_FLD/VIN[0]B_VSYNC/I2C[2]_SCL/GP2[1])
DM388_VIN[0]A_HSYNC: J5.32 U7.D13(VIN[0]A_HSYNC/GP2[3])
DM388_VIN[0]A_VSYNC: J5.19 U7.C13(VIN[0]A_VSYNC/GP2[4])
DM388_VIN[0]B_CLK: J5.44 U7.H12(VIN[0]B_CLK/CLKOUT0/GP1[9])
DM388_WARM_RSTn: J3.48 ; also on sheet 9
EN_LS_3V3: J4.68 ; also on sheet 17
ENET_RSTn: J4.81 U7.L2(VOUT[1]_G_Y_YC[2]/GPMC_A[13]/VIN[1]A_D[21]/HDMI_SCL/SPI[2]_SCS[2]n/I2C[2]_SCL/GP3[20])
HDDAC_A: J5.28 R112.2 U7.A9(HDDAC_A)
HDDAC_B: J5.30 R113.2 U7.A8(HDDAC_B)
HDDAC_C: J5.41 R64.2 U7.B8(HDDAC_C)
HDDAC_HSYNC: J5.36 U7.E9(HDDAC_HSYNC)
HDDAC_VREF: C46.2 R66.2 R68.2 U7.B7(HDDAC_VREF)
HDDAC_VSYNC: J5.38 U7.D9(HDDAC_VSYNC)
OSC_WAKE: J3.73 ; also on sheet 9
PMIC_3V3: C34.1 C37.1 R27.1 TP13.1(TP) ; also on sheet 16
TPS_INT1: J5.2 ; also on sheet 9 17
TPS_VDDA_1V8: J4.24 ; also on sheet 12 13 14 16
TV_OUT0: J3.53 R74.1 U7.B9(TV_OUT0)
VBACKUP: J5.43 ; also on sheet 16
VREF_1.24V: C54.1 D1.4(REF) R68.1 R71.1
N11883885: RA2.4 U7.AK6(EMAC[0]_MTXD[0]/EMAC[1]_RGRXD[3]/GPMC_A[7]/SPI[2]_D[0])
N11883897: RA2.3 U7.AJ7(EMAC[0]_MTXD[1]/EMAC[1]_RGTXD[1]/GPMC_A[8])
N11883909: RA2.2 U7.AK7(EMAC[0]_MTXD[2]//EMAC[1]_RGTXCTL/EMAC[1]_RMRXD[0]/GPMC_A[9])
N11883921: RA2.1 U7.AE4(EMAC[0]_MTXD[3]/EMAC[1]_RGTXD[0]/EMAC[1]_RMRXD[1]/GPMC_A[10])
N11883933: RA3.4 U7.AK8(EMAC[0]_MTXD[4]/EMAC[1]_RGTXD[2]/EMAC[1]_RMRXER/GPMC_A[11])
N11883945: RA3.3 U7.AJ8(EMAC[0]_MTXD[5]/EMAC[1]_RGTXC/EMAC[1]_RMCRSDV/GPMC_A[12]/UART1_RXD)
N11883957: RA3.2 U7.AH8(EMAC[0]_MTXD[6]/EMAC[1]_RGRXD[0]/EMAC[1]_RMTXD[0]/GPMC_A[13]/UART1_TXD)
N11883969: RA3.1 U7.AG8(EMAC[0]_MTXD[7]/EMAC[1]_RGTXD[3]/EMAC[1]_RMTXD[1]/GPMC_A[14]/UART1_CTSn)
N14519770: R63.1 U7.B6(HDDAC_IREF)
N14522090: R73.2 U7.AL6(EMAC[0]_GMTCLK/EMAC[1]_RGRXC/GPMC_A[6]/SPI[2]_D[1])
N14522146: R114.2 U7.AF8(EMAC[0]_MTXEN/EMAC[1]_RGRXD[2]/EMAC[1]_RMTXEN/GPMC_A[15]/UART1_RTSn)
N14559309: R104.1 U7.AJ4(EMAC[0]_MRXD[5]/EMAC[0]_RGTXD[3]/GPMC_A[2])
N14559352: R110.1 U7.AK5(EMAC[0]_MRXD[7]/EMAC[0]_RGTXD[1]/GPMC_A[4]/SPI[2]_SCS[3]n)
N14559366: R111.1 U7.AL5(EMAC[0]_MRXD[6]/EMAC[0]_RGTXD[2]/GPMC_A[3])
N14559434: R109.1 U7.AK2(EMAC[0]_MRXD[0]/EMAC[0]_RGTXD[0]/VIN[1]B_D[5]/EMAC[0]_RMTXD[0]/GP3[28])
N14595953: D1.3(CATHODE) R69.2 R71.2
N14599932: R78.1 U7.B19(EMU1)
N14599936: R77.1 U7.A18(EMU0)
N14600104: R124.1 U7.N29(RTCK)
N14600252: C64.1 U7.K31(PCIE_TXN0)
N14600256: C63.1 U7.L31(PCIE_TXP0)
N14600268: C66.1 U7.H31(SERDES_CLKN)
N14600316: C65.1 U7.H30(SERDES_CLKP)
N14600424: R74.2 U7.B10(TV_VFB0)
N14600444: R76.2 U7.B11(TV_RSET)
N14719324: R106.1 U7.AK1(EMAC[0]_MRCLK/EMAC[0]_RGTXC/VIN[1]B_D[4]/EMAC[0]_RMCRSDV/SPI[3]_SCS[2]n/GP3[27])
N15102988: R65.2 U7.AG2(MDCLK/GP1[11])
N15454827: R133.1 U7.U26(TDO)

Not connected (* = marked no-connect by the designer): D1 1(NC1)* 2(NC2)*; J4 26*; U7 A26(VOUT[0]_G_Y_YC[6])* A27(VOUT[0]_G_Y_YC[9])* A29(VOUT[0]_R_CR[5])* A30(VOUT[0]_R_CR[8])* AD8(RSV41)* AH24(RSV34)* AJ24(RSV35)* B25(VOUT[0]_G_Y_YC[7])* B26(VOUT[0]_G_Y_YC[5])* B27(VOUT[0]_G_Y_YC[8])* B28(VOUT[0]_R_CR[3]/GP2[27])* B29(VOUT[0]_R_CR[4])* B30(VOUT[0]_R_CR[7])* B31(VOUT[0]_R_CR[9])* C20(VOUT[0]_AVID/VOUT[0]_FLD/SPI[3]_SCLK/TIM7_IO/GP2[21])* C24(VOUT[0]_B_CB_C[9])* C25(VOUT[0]_G_Y_YC[2]/EMU3/GP2[24])* C26(VOUT[0]_G_Y_YC[3]/GP2[25])* C28(VOUT[0]_R_CR[2]/EMU4/GP2[26])* C30(VOUT[0]_R_CR[6])* D3(VOUT[1]_CLK/EMAC[1]_MTCLK/VIN[1]A_HSYNC/GP2[28])* D21(VOUT[0]_B_CB_C[3]/GP2[23])* D24(VOUT[0]_B_CB_C[8])* E2(VOUT[1]_HSYNC/EMAC[1]_MCOL/VIN[1]A_VSYNC/SPI[3]_D[1]/GP2[29])* E20(VOUT[0]_VSYNC)* E24(VOUT[0]_B_CB_C[7])* E26(VOUT[0]_G_Y_YC[4])* F1(VOUT[1]_AVID/EMAC[1]_MRXER/VIN[1]A_CLK/TIM6_IO/GP2[31])* F2(VOUT[1]_B_CB_C[3]/EMAC[1]_MRCLK/VIN[1]A_D[0]/GP3[0])* F3(VOUT[1]_B_CB_C[4]/EMAC[1]_MRXD[0]/VIN[1]A_D[1]/GP3[1])* F5(VOUT[1]_VSYNC/EMAC[1]_MCRS/VIN[1]A_FLD/VIN[1]A_DE/SPI[3]_D[0]/GP2[30])* F21(VOUT[0]_HSYNC)* F24(VOUT[0]_B_CB_C[2]/EMU2/GP2[22])* G1(VOUT[1]_B_CB_C[5]/EMAC[1]_MRXD[1]/VIN[1]A_D[2]/GP3[2])* G3(VOUT[1]_B_CB_C[8]/EMAC[1]_MRXD[4]/VIN[1]A_D[5]/I2C[3]_SCL/GP3[5])* H2(VOUT[1]_R_CR[4]/EMAC[1]_MTXD[3]/VIN[1]A_D[15]/SPI[3]_SCS[1]n/GP3[14])* H4(VOUT[1]_G_Y_YC[6]/EMAC[1]_GMTCLK/VIN[1]A_D[11]/GP3[10])* H5(VOUT[1]_B_CB_C[9]/EMAC[1]_MRXD[5]/VIN[1]A_D[6]/I2C[3]_SDA/GP3[6])* H6(VOUT[1]_G_Y_YC[3]/EMAC[1]_MRXD[6]/VIN[1]A_D[8]/GP3[7])* H23(VOUT[0]_B_CB_C[5])* H24(RSV2)* H25(RSV39)* H27(RSV1)* H28(RSV3)* H29(RSV40)* J1(VOUT[1]_G_Y_YC[5]/EMAC[1]_MRXDV/VIN[1]A_D[10]/GP3[9])* J2(VOUT[1]_R_CR[8]/EMAC[1]_MTXD[7]/VIN[1]A_D[19]/GP3[18])* J8(VOUT[1]_G_Y_YC[4]/EMAC[1]_MRXD[7]/VIN[1]A_D[9]/GP3[8])* J9(VOUT[1]_G_Y_YC[7]/EMAC[1]_MTXD[0]/VIN[1]A_D[12]/GP3[11])* J23(VOUT[0]_B_CB_C[4])* J24(VOUT[0]_B_CB_C[6])* J25(RSV0)* K1(VOUT[1]_G_Y_YC[9]/EMAC[1]_MTXD[2]/VIN[1]A_D[14]/GP3[13])* K2(VOUT[1]_R_CR[9]/EMAC[1]_MTXEN/VIN[1]A_D[20]/GP3[19])* K22(VOUT[0]_CLK)* L3(VOUT[1]_G_Y_YC[8]/EMAC[1]_MTXD[1]/VIN[1]A_D[13]/GP3[12])* L4(VOUT[1]_R_CR[3]/GPMC_A[14]/VIN[1]A_D[22]/HDMI_SDA/SPI[2]_SCLK/I2C[2]_SDA/GP3[21])* L6(VOUT[1]_R_CR[2]/GPMC_A[15]/VIN[1]A_D[23]/HDMI_HPDET/SPI[2]_D[1]/GP3[22])* L12(VOUT[1]_R_CR[6]/EMAC[1]_MTXD[5]/VIN[1]A_D[17]/SPI[3]_D[1]/GP3[16])* L30(RSV27)* M8(VOUT[1]_B_CB_C[2]/GPMC_A[0]/VIN[1]A_D[7]/HDMI_CEC/SPI[2]_D[0]/GP3[30])* M10(VOUT[1]_R_CR[7]/EMAC[1]_MTXD[6]/VIN[1]A_D[18]/SPI[3]_D[0]/GP3[17])* M11(VOUT[1]_R_CR[5]/EMAC[1]_MTXD[4]/VIN[1]A_D[16]/SPI[3]_SCLK/GP3[15])* M30(RSV28)* N30(RSV29)* N31(RSV30)* P30(RSV43)* P31(RSV31)* R30(RSV32)* T30(RSV33)*

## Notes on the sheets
sheet 19
- ETHERNET
- HDMI & USB
- 0.5V IS GENERATED FOR HD_DAC VREF
sheet 20
- CAMERA
- JTAG, PCIE, TV OUT
- CSI
sheet 21
- BOARD TO BOARD CONNECTORS
- FX11LA-80S/8-SV(71)
- FX11LA-80P/8-SV(71)
- BOARD TO BOARD TERMINATION
- FX11LA-60P/6-SV(71)
